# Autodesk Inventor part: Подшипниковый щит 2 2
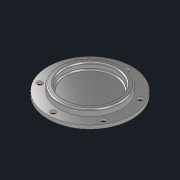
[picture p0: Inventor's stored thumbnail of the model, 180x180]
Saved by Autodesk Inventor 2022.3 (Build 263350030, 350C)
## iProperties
Created: 2022-08
Part Number: Подшипниковый щит 2 2
Material: Сталь 40ХНМА
Document SubType Name: Modeling
Designer: Карташов
Density: 7.85 g/cm^3
Appearance: С умеренной полировкой
Author: Карташов
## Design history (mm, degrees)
sketch "Эскиз1"
  geometry: L1 (0, 0)-(0, 34.001); L2 (30, 0)-(60, 0); L3 (60, 0)-(60, 5); L4 (60, 5)-(45, 5); L5 (45, 5)-(45, 12); L6 (43, 14)-(39, 14); L7 (37, 12)-(37, 7); L8 (35, 5)-(0, 5); L9 (30, 0)-(28, -2); L10 (28, -2)-(0, -2); L11 (0, -2)-(0, 0); A1 r 2 centre (35, 7) between (35, 5) and (37, 7); A2 r 2 centre (43, 12) between (45, 12) and (43, 14); A3 r 2 centre (39, 12) between (39, 14) and (37, 12); 3 further points
  constraints: 22 end point, 6 point on circle, 6 tangent, 5 horizontal, 5 point on line, 3 centre point, 3 vertical, 2 perpendicular, 1 horizontal alignment, 1 midpoint
  dimensions: "d0" = 90 diameter of L5 point (0, 17); "d1" = 120 diameter of L3 L1; "d3" = 14 vertical distance of L2.end point (45, 14); "d4" = 5 distance of L2.end L3.end; "d5" = 9 distance between parallel lines of L8 L6; "d6" = 8 distance of point (45, 14) point (37, 14); "d7" = 2 radius of A1; "d21" = 2 horizontal distance of L2.start L9.end; "d22" = 2 horizontal distance of L2.start L9.end; "d23" = 60 diameter of L2.start L1; "d24" = 2 radius of A2; "d25" = 2 radius of A3 (derived)
revolve "Вращение1" sketch "Эскиз1" stored, may be unused: angle "d9" = 90 deg
sketch "Эскиз2"
  geometry: C1 r 45 at (0, 0) reference; C2 r 60 at (0, 0) reference; 2 further points
  constraints: 1 vertical alignment
  dimensions: "d10" = 52.5 distance of point (0, 0) point (0, -52.5)
  node "Спроецированная петля1"
sketch "Эскиз3"
  geometry: 2 further points
hole "Отверстие1" sketch "Эскиз3" at (0, 52.5) diameter "d11" = 8; stored, may be unused: countersink angle "d15" = 90 deg, drill point angle "d17" = 0 deg; dims "d12" = 6, "d13" = 13, "d14" = 1, "d16" = 22.5
pattern_circular "Круговой массив1" dims angle "d19" = 360 deg
node "Твердое тело1"
